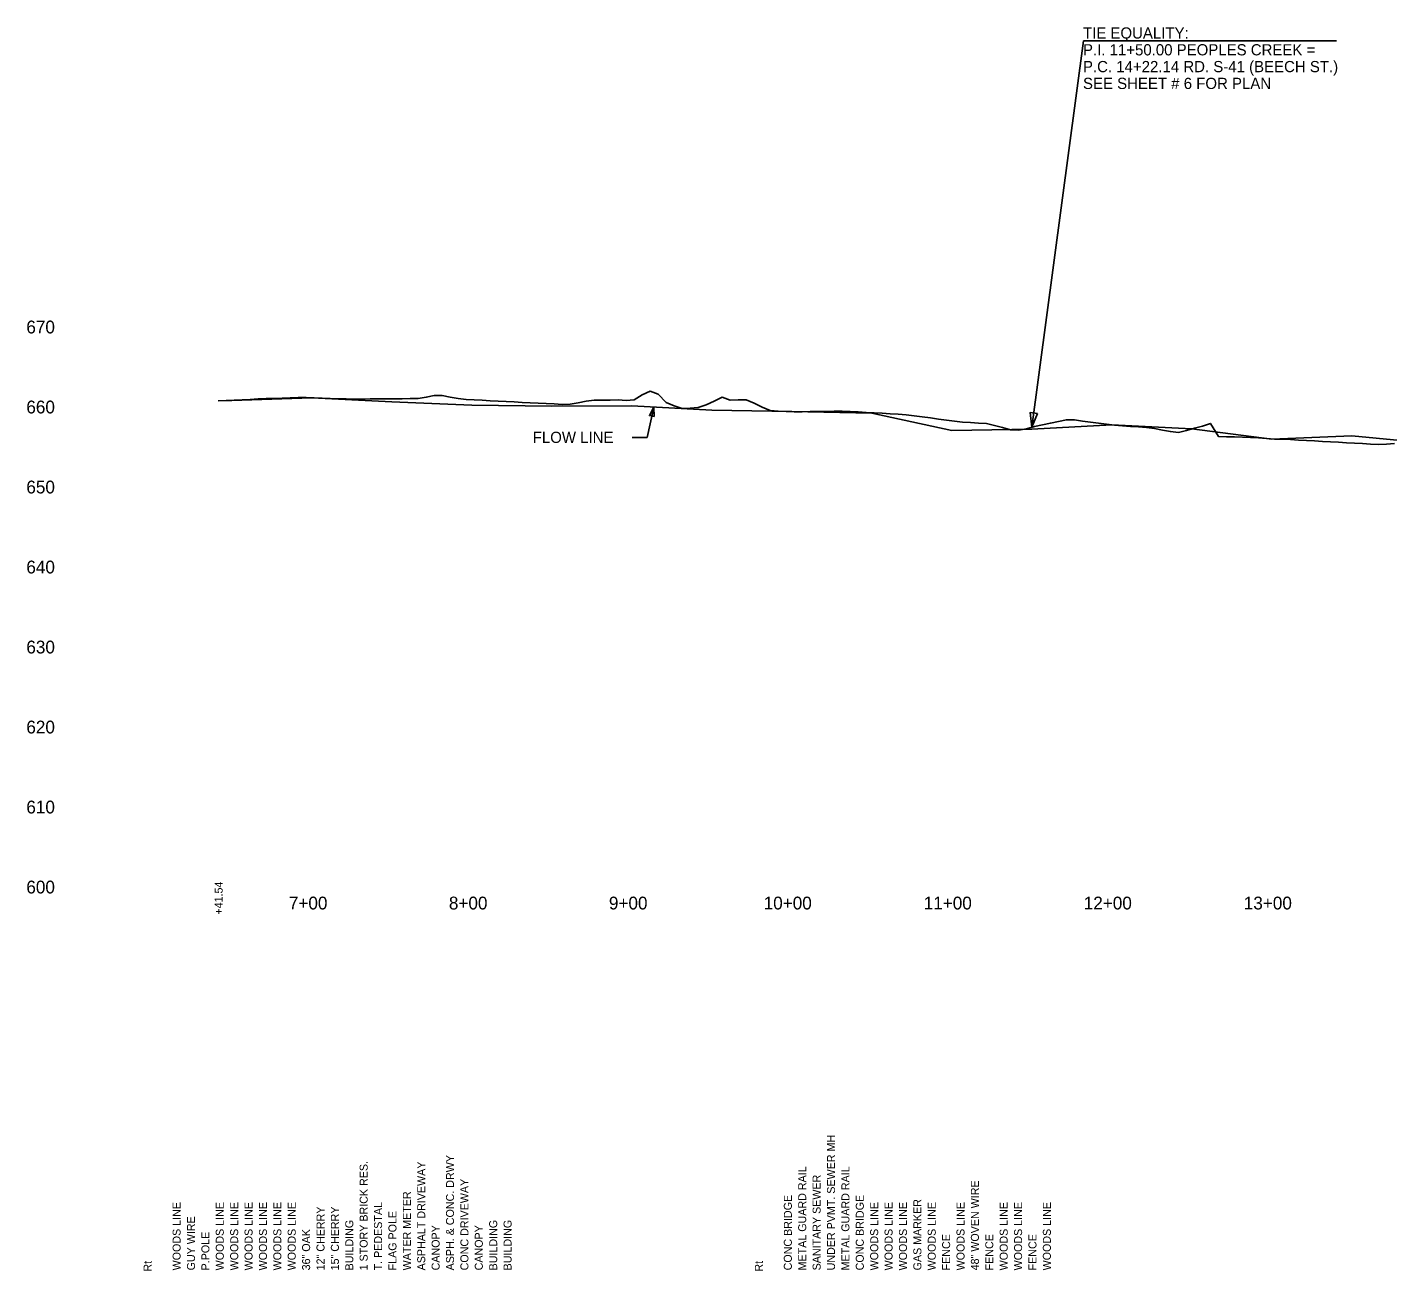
# Model space of a CAD drawing. Extents: x 16382402 to 16388022, y 46194326 to 46202918.
# Drawn here: x 16384274 to 16385124, y 46197686 to 46198463 of the extents above; entities that cross this region are included whole.
import ezdxf

# ---------------------------------------------------------------- set-up
doc = ezdxf.new("R2010")
doc.units = 0
for name, color, linetype in [('RD_DDB_ElevTX', 7, 'Continuous'), ('RD_DDB_Profile_EX', 7, 'Continuous'), ('RD_DDB_Profile_Lbl', 7, 'Continuous'), ('RD_DDB_StaTX', 7, 'Continuous'), ('RD_EX_H2O_WetLd', 7, 'Continuous'), ('RD_HC_Data', 7, 'Continuous'), ('RD_TX_Bldg', 7, 'Continuous'), ('RD_TX_Drainage', 7, 'Continuous'), ('RD_TX_Misc1', 7, 'Continuous')]:
    doc.layers.add(name, color=color, linetype=linetype)

msp = doc.modelspace()

# ---------------------------------------------------------------- linework, layer by layer
at = {"layer": 'RD_DDB_Profile_EX'}
for points in [[(16384392.89, 46198229.64), (16384397.89, 46198229.87), (16384402.89, 46198230.11), (16384407.89, 46198230.35), (16384412.89, 46198230.59), (16384417.89, 46198230.83), (16384422.89, 46198231.04), (16384427.89, 46198231.08), (16384432.89, 46198231.28), (16384437.89, 46198231.49), (16384442.89, 46198231.7), (16384447.89, 46198231.74), (16384452.89, 46198231.61), (16384457.89, 46198231.38), (16384462.89, 46198231.12), (16384467.89, 46198231.01), (16384472.89, 46198230.9), (16384477.89, 46198230.79), (16384482.89, 46198230.77), (16384487.89, 46198230.83), (16384492.89, 46198230.9), (16384497.89, 46198230.93), (16384502.89, 46198230.9), (16384507.89, 46198230.95), (16384512.89, 46198231.08), (16384517.89, 46198231.21), (16384522.89, 46198231.86), (16384527.89, 46198232.95), (16384532.89, 46198232.95), (16384537.89, 46198232.01), (16384542.89, 46198231.08), (16384547.89, 46198230.58), (16384552.89, 46198230.3), (16384557.89, 46198230.01), (16384562.89, 46198229.72), (16384567.89, 46198229.43), (16384572.89, 46198229.16), (16384577.89, 46198228.96), (16384582.89, 46198228.69), (16384587.89, 46198228.42), (16384592.89, 46198228.15), (16384597.89, 46198227.97), (16384602.89, 46198227.78), (16384607.89, 46198227.37), (16384612.89, 46198227.63), (16384617.89, 46198228.49), (16384622.89, 46198229.36), (16384627.89, 46198230.03), (16384632.89, 46198230.1), (16384637.89, 46198230.17), (16384642.89, 46198230.24), (16384647.89, 46198229.91), (16384652.89, 46198230.32), (16384657.89, 46198233.37), (16384662.89, 46198235.68), (16384667.89, 46198233.77), (16384672.89, 46198228.67), (16384677.89, 46198226.63), (16384682.89, 46198224.96), (16384687.89, 46198225.13), (16384692.89, 46198225.42), (16384697.89, 46198227.08), (16384702.89, 46198229.51), (16384707.89, 46198231.94), (16384712.89, 46198230.09), (16384717.89, 46198230.28), (16384722.89, 46198230.35), (16384727.89, 46198228.25), (16384732.89, 46198225.66), (16384737.89, 46198223.7), (16384742.89, 46198223.2), (16384747.89, 46198222.97), (16384752.89, 46198222.8), (16384757.89, 46198222.86), (16384762.89, 46198222.93), (16384767.89, 46198223), (16384772.89, 46198223.07), (16384777.89, 46198223.14), (16384782.89, 46198223.21), (16384787.89, 46198222.98), (16384792.89, 46198222.71), (16384797.89, 46198222.44), (16384802.89, 46198222.17), (16384807.89, 46198221.9), (16384812.89, 46198221.63), (16384817.89, 46198221.35), (16384822.89, 46198220.99), (16384827.89, 46198220.31), (16384832.89, 46198219.62), (16384837.89, 46198218.94), (16384842.89, 46198218.25), (16384847.89, 46198217.56), (16384852.89, 46198216.88), (16384857.89, 46198216.31), (16384862.89, 46198216.05), (16384867.89, 46198215.8), (16384872.89, 46198215.54), (16384877.89, 46198214.35), (16384882.89, 46198212.92), (16384887.89, 46198211.49), (16384892.89, 46198211.37)], [(16384892.89, 46198211.37), (16384897.89, 46198212.18), (16384902.89, 46198213.54), (16384907.89, 46198214.62), (16384912.89, 46198215.71), (16384917.89, 46198216.79), (16384922.89, 46198217.87), (16384927.89, 46198217.77), (16384932.89, 46198217.06), (16384937.89, 46198216.38), (16384942.89, 46198215.77), (16384947.89, 46198215.15), (16384952.89, 46198214.54), (16384957.89, 46198213.99), (16384962.89, 46198213.67), (16384967.89, 46198213.34), (16384972.89, 46198213.01), (16384977.89, 46198212.3), (16384982.89, 46198211.39), (16384987.89, 46198210.49), (16384992.89, 46198209.8), (16384997.89, 46198211.17), (16385002.89, 46198212.55), (16385007.89, 46198213.92), (16385012.89, 46198215.58), (16385017.89, 46198207.43), (16385022.89, 46198207.27), (16385027.89, 46198207.1), (16385032.89, 46198206.94), (16385037.89, 46198206.77), (16385042.89, 46198206.47), (16385047.89, 46198206.08), (16385052.89, 46198205.78), (16385057.89, 46198205.67), (16385062.89, 46198205.41), (16385067.89, 46198205.13), (16385072.89, 46198204.85), (16385077.89, 46198204.57), (16385082.89, 46198204.29), (16385087.89, 46198204.01), (16385092.89, 46198203.73), (16385097.89, 46198203.46), (16385102.89, 46198203.18), (16385107.89, 46198202.9), (16385112.89, 46198202.65), (16385117.89, 46198202.45), (16385122.89, 46198202.66), (16385127.89, 46198203.04)]]:
    msp.add_lwpolyline(points, dxfattribs=at)
at = {"layer": 'RD_EX_H2O_WetLd'}
msp.add_lwpolyline([(16384392.89, 46198229.62), (16384401.35, 46198229.94), (16384451.35, 46198231.49), (16384501.35, 46198228.96), (16384551.35, 46198227.05), (16384601.35, 46198226.33), (16384651.35, 46198226.63), (16384701.35, 46198223.9), (16384751.35, 46198222.99), (16384801.35, 46198221.94), (16384851.35, 46198211.07), (16384901.35, 46198211.92), (16384951.35, 46198214.72), (16385001.35, 46198212.13), (16385051.35, 46198205.81), (16385101.35, 46198207.82), (16385151.35, 46198203), (16385201.35, 46198203.03), (16385251.35, 46198201.92), (16385301.35, 46198200.55), (16385314.17, 46198214.95)], dxfattribs=at)
at = {"layer": 'RD_HC_Data'}
for p, q in [((16384901.35, 46198213.2), (16384933.56, 46198454.64)), ((16384933.56, 46198454.64), (16385091.62, 46198454.64))]:
    msp.add_line(p, q, dxfattribs=at)
at = {"layer": 'RD_TX_Drainage'}
for points in [[(16384665.4, 46198219.81), (16384665.11, 46198225.8), (16384662.37, 46198220.46)], [(16384904.77, 46198221.83), (16384901.35, 46198213.2), (16384900.31, 46198222.42)]]:
    msp.add_lwpolyline(points, close=True, dxfattribs=at)
at = {"layer": 'RD_TX_Misc1'}
for p, q in [((16384660.99, 46198206.74), (16384665.11, 46198225.8)), ((16384651.64, 46198206.74), (16384660.99, 46198206.74))]:
    msp.add_line(p, q, dxfattribs=at)

# ---------------------------------------------------------------- texts
at = {"layer": 'RD_DDB_ElevTX'}
for s, p in [('670', (16384273.02, 46198271.8)), ('660', (16384273.02, 46198221.8)), ('650', (16384273.02, 46198171.8)), ('640', (16384273.02, 46198121.8)), ('630', (16384273.02, 46198071.8)), ('620', (16384273.02, 46198021.8)), ('610', (16384273.02, 46197971.8)), ('600', (16384273.02, 46197921.8))]:
    msp.add_text(s, height=8, dxfattribs=at).set_placement(p)
at = {"layer": 'RD_DDB_Profile_Lbl'}
msp.add_text('FLOW LINE', height=7, dxfattribs=at).set_placement((16384589.45, 46198203.35))
at = {"layer": 'RD_DDB_StaTX'}
msp.add_text('+41.54', height=5, rotation=90, dxfattribs=at).set_placement((16384395.68, 46197908.56))
for s, p in [('7+00', (16384437.06, 46197911.8)), ('7+00', (16384437.06, 46197911.8)), ('8+00', (16384537.06, 46197911.8)), ('8+00', (16384537.06, 46197911.8)), ('9+00', (16384637.06, 46197911.8)), ('9+00', (16384637.06, 46197911.8)), ('10+00', (16384733.76, 46197911.8)), ('10+00', (16384733.76, 46197911.8)), ('11+00', (16384833.76, 46197911.8)), ('11+00', (16384833.76, 46197911.8)), ('12+00', (16384933.76, 46197911.8)), ('12+00', (16384933.76, 46197911.8)), ('13+00', (16385033.76, 46197911.8)), ('13+00', (16385033.76, 46197911.8))]:
    msp.add_text(s, height=8, dxfattribs=at).set_placement(p)
at = {"layer": 'RD_HC_Data'}
for s, p in [('TIE EQUALITY:', (16384933.27, 46198456.06)), ('P.I. 11+50.00 PEOPLES CREEK =', (16384933.27, 46198445.56)), ('P.C. 14+22.14 RD. S-41 (BEECH ST.)', (16384933.27, 46198435.06)), ('SEE SHEET # 6 FOR PLAN', (16384933.27, 46198424.56))]:
    msp.add_text(s, height=7, dxfattribs=at).set_placement(p)
at = {"layer": 'RD_TX_Bldg'}
for s, p in [('UNDER PVMT. SEWER MH', (16384778.33, 46197686.23)), ('ASPH. & CONC. DRWY', (16384540.26, 46197686.23)), ('1 STORY BRICK RES.', (16384486.31, 46197686.23)), ('ASPHALT DRIVEWAY', (16384522.28, 46197686.23)), ('METAL GUARD RAIL', (16384760.34, 46197686.23)), ('METAL GUARD RAIL', (16384787.32, 46197686.23)), ('CONC DRIVEWAY', (16384549.25, 46197686.23)), ('SANITARY SEWER', (16384769.33, 46197686.23)), ('48" WOVEN WIRE', (16384868.24, 46197686.23)), ('WATER METER', (16384513.29, 46197686.23)), ('CONC BRIDGE', (16384751.35, 46197686.23)), ('CONC BRIDGE', (16384796.31, 46197686.23)), ('WOODS LINE', (16384369.42, 46197686.23)), ('WOODS LINE', (16384396.39, 46197686.23)), ('WOODS LINE', (16384405.39, 46197686.23)), ('WOODS LINE', (16384414.38, 46197686.23)), ('WOODS LINE', (16384423.37, 46197686.23)), ('WOODS LINE', (16384432.36, 46197686.23)), ('WOODS LINE', (16384441.35, 46197686.23)), ('12" CHERRY', (16384459.34, 46197686.23)), ('15" CHERRY', (16384468.33, 46197686.23)), ('T. PEDESTAL', (16384495.3, 46197686.23)), ('WOODS LINE', (16384805.3, 46197686.23)), ('WOODS LINE', (16384814.29, 46197686.23)), ('WOODS LINE', (16384823.28, 46197686.23)), ('GAS MARKER', (16384832.28, 46197686.23)), ('WOODS LINE', (16384841.27, 46197686.23)), ('WOODS LINE', (16384859.25, 46197686.23)), ('WOODS LINE', (16384886.23, 46197686.23)), ('WOODS LINE', (16384895.22, 46197686.23)), ('WOODS LINE', (16384913.2, 46197686.23)), ('GUY WIRE', (16384378.41, 46197686.23)), ('BUILDING', (16384477.32, 46197686.23)), ('FLAG POLE', (16384504.29, 46197686.23)), ('BUILDING', (16384567.24, 46197686.23)), ('BUILDING', (16384576.23, 46197686.23)), ('P.POLE', (16384387.4, 46197686.23)), ('36" OAK', (16384450.34, 46197686.23)), ('CANOPY', (16384531.27, 46197686.23)), ('CANOPY', (16384558.25, 46197686.23)), ('FENCE', (16384850.26, 46197686.23)), ('FENCE', (16384877.23, 46197686.23)), ('FENCE', (16384904.21, 46197686.23)), ('Rt', (16384351.3, 46197685.43)), ('Rt', (16384733.24, 46197685.43))]:
    msp.add_text(s, height=5, rotation=90, dxfattribs=at).set_placement(p)

doc.saveas('drawing.dxf')
